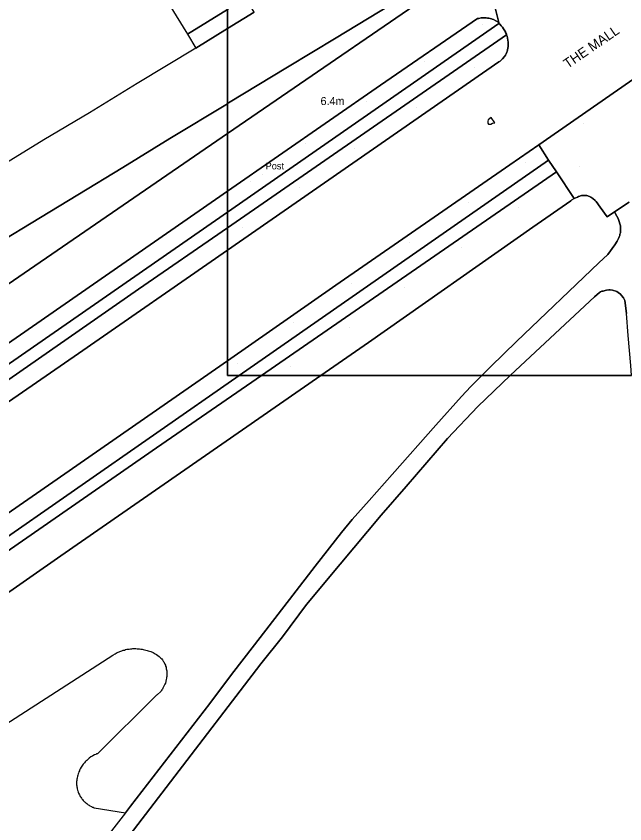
# Model space of a CAD drawing. Extents: x 529240 to 530363, y 179600 to 180767.
# Drawn here: x 529670.1 to 529802.4, y 180016.5 to 180192.1 of the extents above; entities that cross this region are included whole.
import ezdxf

# ---------------------------------------------------------------- set-up
doc = ezdxf.new("R2010")
doc.units = 0
for name, color, linetype in [('Building', 7, 'Continuous'), ('General surface', 7, 'Continuous'), ('Natural environment', 7, 'Continuous'), ('Path', 7, 'Continuous'), ('Road Or Track', 7, 'Continuous'), ('Roadside', 7, 'Continuous'), ('Unclassified', 7, 'Continuous')]:
    doc.layers.add(name, color=color, linetype=linetype)

msp = doc.modelspace()

# ---------------------------------------------------------------- linework, layer by layer
at = {"layer": 'Building'}
for points in [[(529716, 180193.58), (529716, 180202.74), (529709.2, 180214.1), (529706.65, 180212.55), (529704.8, 180215.45), (529704.55, 180215.8), (529700.4, 180213.2), (529701.7, 180211.15), (529702.45, 180210), (529696.3, 180206.1), (529707.3, 180188.2)], [(529716, 180189.42), (529721.85, 180193), (529720, 180196.05), (529716, 180193.58)], [(529716, 180189.42), (529716, 180193.58), (529707.3, 180188.2), (529709.1, 180185.2)]]:
    msp.add_lwpolyline(points, close=True, dxfattribs=at)
for points in [[(529716, 180193.58), (529707.3, 180188.2)], [(529721.85, 180193), (529716, 180189.42)], [(529716, 180189.42), (529709.1, 180185.2)]]:
    msp.add_lwpolyline(points, dxfattribs=at)
at = {"layer": 'General surface'}
for points in [[(529721.85, 180193), (529716, 180189.42), (529716, 180173.09), (529716.27, 180173.25), (529729.1, 180181.05), (529739.62, 180187.44), (529770, 180205.9)], [(529500, 180004.5), (529589.65, 180066.45), (529716, 180154.06), (529716, 180166.62), (529643, 180116.55), (529637.65, 180125.3), (529631.8, 180121.7), (529630.55, 180123.8), (529627.87, 180122.15), (529629.1, 180120.1), (529627.36, 180119.04), (529622.49, 180116.08), (529620.8, 180115.05), (529619.57, 180117.04), (529616.9, 180115.4), (529618.1, 180113.4), (529617.4, 180112.8), (529612.15, 180109.6), (529618.4, 180099.65), (529597.85, 180085.45), (529594.65, 180083.25), (529500, 180018.5), (529488.6, 180010.4)]]:
    msp.add_lwpolyline(points, dxfattribs=at)
for points in [[(529716, 180166.62), (529771, 180204.35), (529770, 180205.9), (529739.62, 180187.44), (529729.1, 180181.05), (529716.27, 180173.25), (529716, 180173.09)], [(529716, 180166.62), (529716, 180154.06), (529749.3, 180177.15), (529770.35, 180191.6), (529770.65, 180191.65), (529771.15, 180191.75), (529772.25, 180191.75), (529772.55, 180191.7), (529772.85, 180191.7), (529773.15, 180191.65), (529773.45, 180191.55), (529773.55, 180191.5), (529773.85, 180191.4), (529774.35, 180191.1), (529774.99, 180190.74), (529773.91, 180195.12), (529771, 180204.35)], [(529716, 180154.06), (529716, 180149.52), (529775.05, 180190.5), (529774.99, 180190.74), (529774.35, 180191.1), (529773.85, 180191.4), (529773.55, 180191.5), (529773.45, 180191.55), (529773.15, 180191.65), (529772.85, 180191.7), (529772.55, 180191.7), (529772.25, 180191.75), (529771.15, 180191.75), (529770.65, 180191.65), (529770.35, 180191.6), (529749.3, 180177.15)], [(529716, 180173.09), (529716, 180189.42), (529709.1, 180185.2), (529696.4, 180177.45), (529686, 180171.1), (529676.1, 180165.2), (529666, 180159.05), (529665.5, 180159.9), (529663.75, 180158.9), (529664.3, 180158), (529663.1, 180157.3), (529663.6, 180156.55), (529654.8, 180151.1), (529656.05, 180149), (529651.8, 180146.45), (529657.35, 180137.45), (529683.44, 180153.3), (529693.23, 180159.25), (529703.5, 180165.49)], [(529716, 180166.62), (529716, 180173.09), (529703.5, 180165.49), (529693.23, 180159.25), (529683.44, 180153.3), (529657.35, 180137.45), (529637.65, 180125.3), (529643, 180116.55)], [(529723.41, 180114), (529736.32, 180114), (529746.7, 180121.2), (529782.4, 180146.25), (529790.65, 180151.95), (529790.9, 180152.15), (529791.4, 180152.45), (529787.55, 180158.3)], [(529716, 180154.06), (529589.65, 180066.45), (529500, 180004.5), (529497.55, 180002.65), (529493.63, 180000), (529470.3, 179984.2), (529472.8, 179980.7), (529498.55, 179999.05), (529500, 180000), (529578.2, 180053.9), (529716, 180149.52)], [(529723.41, 180114), (529700.6, 180098.25), (529630.85, 180049.95), (529559.28, 180000), (529500.2, 179958.75), (529500, 179958.8), (529492.3, 179953.4), (529494.3, 179950.2), (529495.3, 179950.8), (529497.4, 179947.9), (529500, 179949.7), (529510.5, 179956.9), (529525.55, 179967.55), (529542.6, 179979.4), (529558.75, 179990.65), (529572.28, 180000), (529586.1, 180009.55), (529628.15, 180038.75), (529679.8, 180074.8), (529736.32, 180114)]]:
    msp.add_lwpolyline(points, close=True, dxfattribs=at)
at = {"layer": 'Natural environment'}
for points in [[(529736.32, 180114), (529771.33, 180114), (529773.3, 180115.95), (529778.85, 180121.4), (529796.8, 180138.5), (529798.75, 180140.3), (529800.25, 180142.4), (529800.75, 180143.2), (529801.05, 180143.8), (529801.2, 180144.15), (529801.3, 180144.45), (529801.35, 180144.7), (529801.45, 180145), (529801.45, 180145.3), (529801.5, 180145.65), (529801.5, 180146.1), (529801.45, 180146.5), (529801.05, 180147.9), (529800.95, 180148.1), (529800.7, 180148.65), (529800.2, 180149.55), (529798.6, 180148.5), (529797.05, 180150.6), (529796.2, 180151.8), (529795.95, 180152.05), (529795.45, 180152.45), (529795, 180152.75), (529794.75, 180152.9), (529794.15, 180153.1), (529793.8, 180153.15), (529793, 180153.15), (529792.8, 180153.05), (529792.6, 180153), (529792.35, 180152.9), (529792.15, 180152.8), (529791.4, 180152.45), (529790.9, 180152.15), (529790.65, 180151.95), (529782.4, 180146.25), (529746.7, 180121.2)], [(529777.5, 180114), (529803.89, 180114), (529803.7, 180116.15), (529803.15, 180122.7), (529802.8, 180127.45), (529802.4, 180130.3), (529802.1, 180130.9), (529801.7, 180131.4), (529801.45, 180131.65), (529800.95, 180132.05), (529800.65, 180132.25), (529799.75, 180132.55), (529799.25, 180132.65), (529798.95, 180132.65), (529798.45, 180132.55), (529798.15, 180132.5), (529797.7, 180132.35), (529797.4, 180132.3), (529797.1, 180132.15), (529796.9, 180132), (529795.8, 180131.1), (529778.65, 180115.1)]]:
    msp.add_lwpolyline(points, close=True, dxfattribs=at)
for points in [[(529608.5, 180000), (529691.1, 180053.2), (529691.6, 180053.5), (529691.8, 180053.6), (529692.05, 180053.75), (529693.05, 180054.15), (529693.35, 180054.25), (529693.6, 180054.3), (529693.85, 180054.4), (529694.1, 180054.45), (529694.4, 180054.5), (529694.65, 180054.5), (529694.95, 180054.55), (529695.2, 180054.55), (529695.45, 180054.6), (529696.05, 180054.6), (529696.35, 180054.55), (529696.9, 180054.55), (529697.15, 180054.5), (529697.45, 180054.45), (529697.7, 180054.4), (529698, 180054.35), (529698.25, 180054.3), (529698.55, 180054.2), (529698.8, 180054.15), (529699.05, 180054.05), (529699.35, 180053.95), (529699.85, 180053.75), (529700.05, 180053.6), (529700.3, 180053.5), (529700.55, 180053.35), (529701.15, 180052.9), (529701.55, 180052.5), (529701.75, 180052.35), (529701.9, 180052.15), (529702.05, 180051.9), (529702.2, 180051.7), (529702.4, 180051.2), (529702.5, 180051), (529702.55, 180050.8), (529702.65, 180050.6), (529702.7, 180050.4), (529702.7, 180050.2), (529702.8, 180049.8), (529702.8, 180049.35), (529702.85, 180049.15), (529702.8, 180048.95), (529702.8, 180048.55), (529702.75, 180048.35), (529702.75, 180048.15), (529702.7, 180047.9), (529702.5, 180047.1), (529702.4, 180046.9), (529702.35, 180046.75), (529702.05, 180046.15), (529701.95, 180046), (529701.85, 180045.8), (529701.75, 180045.65), (529701.6, 180045.45), (529701.5, 180045.3), (529700.75, 180044.55), (529700.6, 180044.45), (529700.4, 180044.3), (529687.75, 180031.75), (529687.55, 180031.7), (529687.35, 180031.6), (529687.1, 180031.5), (529686.7, 180031.3), (529686.5, 180031.15), (529686.3, 180031.05), (529685.9, 180030.75), (529685.75, 180030.6), (529685.55, 180030.45), (529685.4, 180030.3), (529685.2, 180030.15), (529685.05, 180029.95), (529684.9, 180029.8), (529684.75, 180029.6), (529684.6, 180029.45), (529684.45, 180029.25), (529684.35, 180029.05), (529684.2, 180028.85), (529684, 180028.45), (529683.85, 180028.2), (529683.8, 180028), (529683.7, 180027.8), (529683.6, 180027.55), (529683.55, 180027.35), (529683.45, 180027.1), (529683.4, 180026.9), (529683.3, 180026.4), (529683.25, 180026.2), (529683.25, 180025.95), (529683.2, 180025.7), (529683.2, 180025), (529683.25, 180024.8), (529683.25, 180024.55), (529683.3, 180024.3), (529683.35, 180024.1), (529683.4, 180023.85), (529683.45, 180023.65), (529683.55, 180023.4), (529683.6, 180023.2), (529683.8, 180022.8), (529683.9, 180022.65), (529684, 180022.45), (529684.1, 180022.3), (529684.25, 180022.1), (529684.35, 180021.95), (529684.5, 180021.8), (529684.6, 180021.6), (529684.9, 180021.3), (529685.05, 180021.2), (529685.2, 180021.05), (529685.4, 180020.9), (529685.55, 180020.8), (529685.7, 180020.65), (529685.9, 180020.55), (529686.05, 180020.45), (529686.45, 180020.25), (529686.6, 180020.15), (529686.8, 180020.1), (529687, 180020), (529693.8, 180018.9), (529694.9, 180020.35), (529712.15, 180042.65), (529716.9, 180048.95), (529721.9, 180055.4), (529730.2, 180066.25), (529735.1, 180072.55), (529740.8, 180079.85), (529743.15, 180082.7), (529746.8, 180086.8), (529751.8, 180092.45), (529761.35, 180103.2), (529766.9, 180109.4), (529768.9, 180111.6), (529771.33, 180114), (529736.32, 180114), (529679.8, 180074.8), (529628.15, 180038.75)], [(529803.89, 180114), (529777.5, 180114), (529770.45, 180107.25), (529763.85, 180100.3), (529754.9, 180089.85), (529749.45, 180083.65), (529740.5, 180073), (529733.2, 180064.2), (529727.95, 180057.15), (529723.3, 180051.3), (529684, 180000)]]:
    msp.add_lwpolyline(points, dxfattribs=at)
at = {"layer": 'Path'}
for points in [[(529716, 180149.52), (529716, 180146.12), (529776.7, 180188.05), (529776.7, 180188.2), (529776.5, 180188.55), (529776.45, 180188.7), (529776.05, 180189.4), (529775.85, 180189.7), (529775.55, 180190.05), (529775.25, 180190.35), (529775.05, 180190.5)], [(529718.57, 180114), (529723.41, 180114), (529787.55, 180158.3), (529785.85, 180160.8)]]:
    msp.add_lwpolyline(points, close=True, dxfattribs=at)
for points in [[(529803.35, 180151.65), (529800.2, 180149.55), (529800.7, 180148.65), (529800.95, 180148.1), (529801.05, 180147.9), (529801.45, 180146.5), (529801.5, 180146.1), (529801.5, 180145.65), (529801.45, 180145.3), (529801.45, 180145), (529801.35, 180144.7), (529801.3, 180144.45), (529801.2, 180144.15), (529801.05, 180143.8), (529800.75, 180143.2), (529800.25, 180142.4), (529798.75, 180140.3), (529796.8, 180138.5), (529778.85, 180121.4), (529773.3, 180115.95), (529771.33, 180114), (529777.5, 180114), (529778.65, 180115.1), (529795.8, 180131.1), (529796.9, 180132), (529797.1, 180132.15), (529797.4, 180132.3), (529797.7, 180132.35), (529798.15, 180132.5), (529798.45, 180132.55), (529798.95, 180132.65), (529799.25, 180132.65), (529799.75, 180132.55), (529800.65, 180132.25), (529800.95, 180132.05), (529801.45, 180131.65), (529801.7, 180131.4), (529802.1, 180130.9), (529802.4, 180130.3), (529802.8, 180127.45)], [(529506.1, 180000), (529535.1, 180020.45), (529612, 180073.8), (529696.65, 180132.75), (529716, 180146.12), (529716, 180149.52), (529578.2, 180053.9), (529500, 180000)], [(529559.28, 180000), (529630.85, 180049.95), (529700.6, 180098.25), (529723.41, 180114), (529718.57, 180114), (529646.9, 180064.15), (529554.43, 180000)], [(529684, 180000), (529723.3, 180051.3), (529727.95, 180057.15), (529733.2, 180064.2), (529740.5, 180073), (529749.45, 180083.65), (529754.9, 180089.85), (529763.85, 180100.3), (529770.45, 180107.25), (529777.5, 180114), (529771.33, 180114), (529768.9, 180111.6), (529766.9, 180109.4), (529761.35, 180103.2), (529751.8, 180092.45), (529746.8, 180086.8), (529743.15, 180082.7), (529740.8, 180079.85), (529735.1, 180072.55), (529730.2, 180066.25), (529721.9, 180055.4), (529716.9, 180048.95), (529712.15, 180042.65), (529694.9, 180020.35), (529693.8, 180018.9), (529679.15, 180000)]]:
    msp.add_lwpolyline(points, dxfattribs=at)
at = {"layer": 'Road Or Track'}
for points in [[(529774.99, 180190.74), (529773.91, 180195.12), (529771, 180204.35)], [(529773.91, 180195.12), (529774.99, 180190.74), (529775.05, 180190.5), (529775.25, 180190.35), (529775.55, 180190.05), (529775.85, 180189.7), (529776.05, 180189.4), (529776.45, 180188.7), (529776.5, 180188.55), (529776.7, 180188.2), (529776.7, 180188.05), (529776.8, 180187.75), (529776.9, 180187.35), (529777, 180186.9), (529777.05, 180186.45), (529777.05, 180185.5), (529777, 180185.15), (529776.8, 180184.45), (529776.75, 180184.3), (529776.6, 180183.95), (529776.45, 180183.65), (529776.25, 180183.35), (529775.85, 180182.85), (529775.6, 180182.6), (529775.3, 180182.35), (529775.05, 180182.2), (529716, 180141.23), (529716, 180117.19), (529739.6, 180133.6), (529777.4, 180159.8), (529783.7, 180164.15), (529813.65, 180184.95)], [(529776.7, 180188.05), (529776.7, 180188.2), (529776.5, 180188.55), (529776.45, 180188.7), (529776.05, 180189.4), (529775.85, 180189.7), (529775.55, 180190.05), (529775.25, 180190.35), (529775.05, 180190.5)], [(529716, 180141.23), (529775.05, 180182.2), (529775.3, 180182.35), (529775.6, 180182.6), (529775.85, 180182.85), (529776.25, 180183.35), (529776.45, 180183.65), (529776.6, 180183.95), (529776.75, 180184.3), (529776.8, 180184.45), (529777, 180185.15), (529777.05, 180185.5), (529777.05, 180186.45), (529777, 180186.9), (529776.9, 180187.35), (529776.8, 180187.75), (529776.7, 180188.05)], [(529783.7, 180164.15), (529813.65, 180184.95), (529814.7, 180185.55), (529815.7, 180186.1), (529816.85, 180186.55), (529817.61, 180186.84)], [(529772.67, 180169.59), (529772.6, 180169.26), (529772.61, 180168.82), (529772.79, 180168.65), (529773, 180168.61), (529773.31, 180168.65), (529773.67, 180168.88), (529774.12, 180168.94), (529773.38, 180170.07), (529772.67, 180169.59)], [(529716, 180117.19), (529739.6, 180133.6), (529777.4, 180159.8), (529783.7, 180164.15)], [(529476.2, 179975.55), (529476.4, 179975.7), (529500, 179991.8), (529500.1, 179991.8), (529511.83, 180000), (529585.2, 180050.85), (529683.6, 180118.75), (529716, 180141.23)], [(529490.91, 179961.3), (529500, 179967.55), (529547, 180000), (529678.05, 180090.8), (529716, 180117.19)]]:
    msp.add_lwpolyline(points, dxfattribs=at)
for points in [[(529772.6, 180169.26), (529772.61, 180168.82), (529772.79, 180168.65), (529773, 180168.61), (529773.31, 180168.65), (529773.67, 180168.88), (529774.12, 180168.94), (529773.38, 180170.07), (529772.67, 180169.59)], [(529716, 180141.23), (529683.6, 180118.75), (529585.2, 180050.85), (529511.83, 180000), (529500.1, 179991.8), (529500, 179991.8), (529476.4, 179975.7), (529476.2, 179975.55), (529475.9, 179975.3), (529475.4, 179975.05), (529474.8, 179974.8), (529474.2, 179974.6), (529473.6, 179974.5), (529472.95, 179974.5), (529472.35, 179974.55), (529471.7, 179974.65), (529471.05, 179974.8), (529470.62, 179975.07), (529490.91, 179961.3), (529500, 179967.55), (529547, 180000), (529678.05, 180090.8), (529716, 180117.19)]]:
    msp.add_lwpolyline(points, close=True, dxfattribs=at)
at = {"layer": 'Roadside'}
msp.add_line((529723.55, 180157.8), (529723.55, 180157.8), dxfattribs=at)
for points in [[(529716, 180146.12), (529716, 180141.23), (529775.05, 180182.2), (529775.3, 180182.35), (529775.6, 180182.6), (529775.85, 180182.85), (529776.25, 180183.35), (529776.45, 180183.65), (529776.6, 180183.95), (529776.75, 180184.3), (529776.8, 180184.45), (529777, 180185.15), (529777.05, 180185.5), (529777.05, 180186.45), (529777, 180186.9), (529776.9, 180187.35), (529776.8, 180187.75), (529776.7, 180188.05)], [(529772.67, 180169.59), (529772.6, 180169.26), (529772.61, 180168.82), (529772.79, 180168.65), (529773, 180168.61), (529773.31, 180168.65), (529773.67, 180168.88), (529774.12, 180168.94), (529773.38, 180170.07)], [(529716, 180117.19), (529716, 180114), (529718.57, 180114), (529785.85, 180160.8), (529783.7, 180164.15), (529777.4, 180159.8), (529739.6, 180133.6)], [(529716, 180146.12), (529696.65, 180132.75), (529612, 180073.8), (529535.1, 180020.45), (529506.1, 180000), (529500.15, 179995.9), (529500, 179995.9), (529474.4, 179978.25), (529476.2, 179975.55), (529476.4, 179975.7), (529500, 179991.8), (529500.1, 179991.8), (529511.83, 180000), (529585.2, 180050.85), (529683.6, 180118.75), (529716, 180141.23)], [(529716, 180117.19), (529678.05, 180090.8), (529547, 180000), (529500, 179967.55), (529490.91, 179961.3), (529488, 179959.3), (529490.4, 179956.05), (529500, 179962.4), (529500.15, 179962.3), (529554.43, 180000), (529646.9, 180064.15), (529718.57, 180114), (529716, 180114)]]:
    msp.add_lwpolyline(points, close=True, dxfattribs=at)
msp.add_lwpolyline([(529813.65, 180184.95), (529783.7, 180164.15), (529785.85, 180160.8), (529787.55, 180158.3), (529791.4, 180152.45), (529792.15, 180152.8), (529792.35, 180152.9), (529792.6, 180153), (529792.8, 180153.05), (529793, 180153.15), (529793.8, 180153.15), (529794.15, 180153.1), (529794.75, 180152.9), (529795, 180152.75), (529795.45, 180152.45), (529795.95, 180152.05), (529796.2, 180151.8), (529797.05, 180150.6), (529798.6, 180148.5), (529800.2, 180149.55), (529803.35, 180151.65)], dxfattribs=at)
at = {"layer": 'Unclassified'}
for p, q in [((529771.5, 180190.35), (529771.5, 180190.35)), ((529758.8, 180182.3), (529758.8, 180182.3)), ((529769.65, 180180.95), (529769.65, 180180.95)), ((529738.25, 180173.6), (529738.25, 180173.6)), ((529746.2, 180173.55), (529746.2, 180173.55)), ((529757.05, 180172.35), (529757.05, 180172.35)), ((529793.4, 180168.75), (529793.4, 180168.75)), ((529733.05, 180164.4), (529733.05, 180164.4)), ((529743.65, 180163.25), (529743.65, 180163.25)), ((529780.8, 180160.25), (529780.8, 180160.25)), ((529792.6, 180159.35), (529792.6, 180159.35)), ((529721.1, 180156.1), (529721.1, 180156.1)), ((529731.65, 180154.95), (529731.65, 180154.95)), ((529768.45, 180151.55), (529768.45, 180151.55)), ((529779.2, 180150.6), (529779.2, 180150.6)), ((529719.25, 180146.15), (529719.25, 180146.15)), ((529755.65, 180142.9), (529755.65, 180142.9)), ((529767, 180141.75), (529767, 180141.75)), ((529743, 180134.1), (529743, 180134.1)), ((529754.5, 180133.1), (529754.5, 180133.1)), ((529730.45, 180125.55), (529730.45, 180125.55)), ((529742.6, 180124.45), (529742.6, 180124.45)), ((529718.2, 180116.7), (529718.2, 180116.7)), ((529729.75, 180115.95), (529729.75, 180115.95))]:
    msp.add_line(p, q, dxfattribs=at)
for points in [[(529716, 180173.09), (529716.27, 180173.25), (529729.1, 180181.05), (529739.62, 180187.44), (529770, 180205.9)], [(529771, 180204.35), (529716, 180166.62)], [(529774.99, 180190.74), (529774.35, 180191.1), (529773.85, 180191.4), (529773.55, 180191.5), (529773.45, 180191.55), (529773.15, 180191.65), (529772.85, 180191.7), (529772.55, 180191.7), (529772.25, 180191.75), (529771.15, 180191.75), (529770.65, 180191.65), (529770.35, 180191.6), (529749.3, 180177.15), (529716, 180154.06)], [(529716, 180149.52), (529775.05, 180190.5)], [(529775.05, 180190.5), (529774.99, 180190.74)], [(529776.7, 180188.05), (529716, 180146.12)], [(529657.35, 180137.45), (529683.44, 180153.3), (529693.23, 180159.25), (529703.5, 180165.49), (529716, 180173.09)], [(529716, 180166.62), (529643, 180116.55), (529637.65, 180125.3)], [(529783.7, 180164.15), (529785.85, 180160.8)], [(529785.85, 180160.8), (529718.57, 180114)], [(529785.85, 180160.8), (529787.55, 180158.3)], [(529723.41, 180114), (529787.55, 180158.3)], [(529787.55, 180158.3), (529791.4, 180152.45)], [(529716, 180154.06), (529589.65, 180066.45), (529500, 180004.5), (529497.55, 180002.65), (529493.63, 180000), (529470.3, 179984.2)], [(529800.2, 180149.55), (529798.6, 180148.5), (529797.05, 180150.6), (529796.2, 180151.8), (529795.95, 180152.05), (529795.45, 180152.45), (529795, 180152.75), (529794.75, 180152.9), (529794.15, 180153.1), (529793.8, 180153.15), (529793, 180153.15), (529792.8, 180153.05), (529792.6, 180153), (529792.35, 180152.9), (529792.15, 180152.8), (529791.4, 180152.45)], [(529791.4, 180152.45), (529790.9, 180152.15), (529790.65, 180151.95), (529782.4, 180146.25), (529746.7, 180121.2), (529736.32, 180114)], [(529800.2, 180149.55), (529803.35, 180151.65)], [(529498.55, 179999.05), (529500, 180000), (529578.2, 180053.9), (529716, 180149.52)], [(529796.8, 180138.5), (529798.75, 180140.3), (529800.25, 180142.4), (529800.75, 180143.2), (529801.05, 180143.8), (529801.2, 180144.15), (529801.3, 180144.45), (529801.35, 180144.7), (529801.45, 180145), (529801.45, 180145.3), (529801.5, 180145.65), (529801.5, 180146.1), (529801.45, 180146.5), (529801.05, 180147.9), (529800.95, 180148.1), (529800.7, 180148.65), (529800.2, 180149.55)], [(529716, 180146.12), (529696.65, 180132.75), (529612, 180073.8), (529535.1, 180020.45), (529506.1, 180000), (529500.15, 179995.9), (529500, 179995.9), (529474.4, 179978.25), (529476.2, 179975.55)], [(529771.33, 180114), (529773.3, 180115.95), (529778.85, 180121.4), (529796.8, 180138.5)], [(529803.89, 180114), (529803.7, 180116.15), (529803.15, 180122.7), (529802.8, 180127.45), (529802.4, 180130.3), (529802.1, 180130.9), (529801.7, 180131.4), (529801.45, 180131.65), (529800.95, 180132.05), (529800.65, 180132.25), (529799.75, 180132.55), (529799.25, 180132.65), (529798.95, 180132.65), (529798.45, 180132.55), (529798.15, 180132.5), (529797.7, 180132.35), (529797.4, 180132.3), (529797.1, 180132.15), (529796.9, 180132), (529795.8, 180131.1), (529778.65, 180115.1), (529777.5, 180114)], [(529718.57, 180114), (529646.9, 180064.15), (529554.43, 180000), (529500.15, 179962.3), (529500, 179962.4), (529490.4, 179956.05), (529488, 179959.3)], [(529494.3, 179950.2), (529492.3, 179953.4), (529500, 179958.8), (529500.2, 179958.75), (529559.28, 180000), (529630.85, 180049.95), (529700.6, 180098.25), (529723.41, 180114)], [(529736.32, 180114), (529679.8, 180074.8), (529628.15, 180038.75), (529586.1, 180009.55), (529572.28, 180000), (529558.75, 179990.65), (529542.6, 179979.4), (529525.55, 179967.55), (529510.5, 179956.9), (529500, 179949.7), (529497.4, 179947.9)], [(529777.5, 180114), (529770.45, 180107.25), (529763.85, 180100.3), (529754.9, 180089.85), (529749.45, 180083.65), (529740.5, 180073), (529733.2, 180064.2), (529727.95, 180057.15), (529723.3, 180051.3), (529684, 180000)], [(529693.8, 180018.9), (529694.9, 180020.35), (529712.15, 180042.65), (529716.9, 180048.95), (529721.9, 180055.4), (529730.2, 180066.25), (529735.1, 180072.55), (529740.8, 180079.85), (529743.15, 180082.7), (529746.8, 180086.8), (529751.8, 180092.45), (529761.35, 180103.2), (529766.9, 180109.4), (529768.9, 180111.6), (529771.33, 180114)]]:
    msp.add_lwpolyline(points, dxfattribs=at)

# ---------------------------------------------------------------- texts
at = {"layer": 'Road Or Track'}
msp.add_text('THE MALL', height=2.125, rotation=34.5, dxfattribs=at).set_placement((529790, 180180.65))
at = {"layer": 'Roadside'}
msp.add_text('Post', height=1.5, dxfattribs=at).set_placement((529724.3, 180158.8))
at = {"layer": 'Unclassified'}
msp.add_text('6.4m', height=1.75, dxfattribs=at).set_placement((529736.25, 180172.8))

doc.saveas('drawing.dxf')
